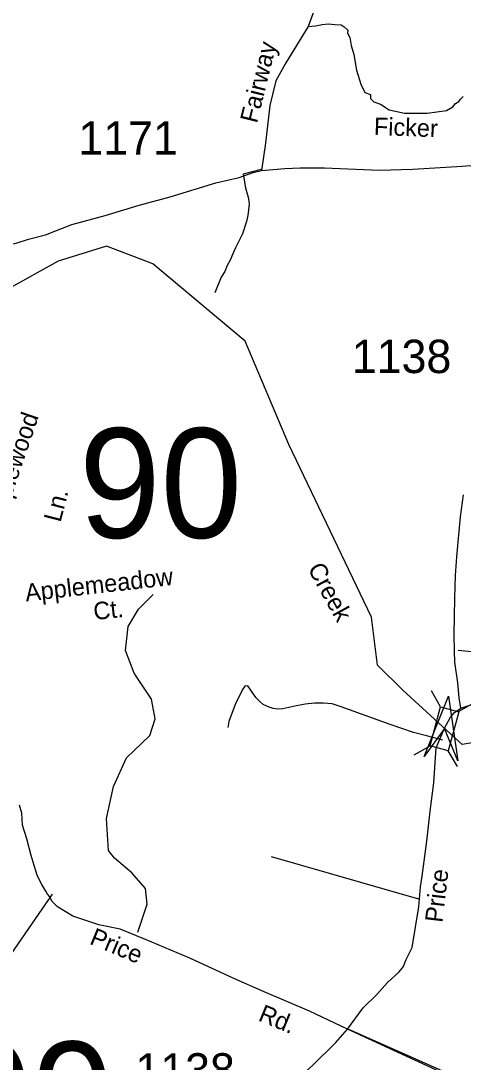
# Model space of a CAD drawing. Extents: x 884530 to 1028605, y 526725 to 653634.
# Drawn here: x 959170 to 960824, y 578430 to 582326 of the extents above; entities that cross this region are included whole.
import ezdxf

# ---------------------------------------------------------------- set-up
doc = ezdxf.new("R2010")
doc.units = 0
for name, color, linetype in [('Exist Hydrographic Creek Single Shore', 7, 'Continuous'), ('Exist Hydrographic Creek Single Shore Label', 7, 'Continuous'), ('Exist Road Non-System Type 51', 7, 'Continuous'), ('Exist Road Non-System Type 51 Label', 7, 'Continuous'), ('Exist Road Secondary Structure Standard Bridge Attributed CELL', 7, 'Continuous'), ('Exist Road Secondary Structure Standard Bridge CELL', 7, 'Continuous'), ('Exist Road Secondary Structure Standard Bridge Number Label', 7, 'Continuous'), ('Exist Road Secondary Type 41 Attributed', 7, 'Continuous'), ('Exist Road Secondary Type 51 Attributed', 7, 'Continuous'), ('Exist Road Secondary Type 51 Label', 7, 'Continuous'), ('Exist Road Secondary Type 51 Number Label', 7, 'Continuous')]:
    doc.layers.add(name, color=color, linetype=linetype)

msp = doc.modelspace()

# ---------------------------------------------------------------- linework, layer by layer
at = {"layer": 'Exist Hydrographic Creek Single Shore'}
msp.add_lwpolyline([(961320.5, 579627.6), (961311.7, 579618.6), (961235.3, 579586.3), (961201.6, 579581.8), (961157.8, 579589.6), (961042.1, 579604.3), (960967.9, 579615.5), (960925.2, 579632.4), (960888.2, 579629), (960821.3, 579618.6), (960598.8, 579821), (960504.4, 579915.4), (960482.1, 580094.7), (960172.1, 580740.4), (960009.5, 581126.8), (959664, 581416.7), (959491.2, 581482.7), (959310.4, 581426), (958932.1, 581217.6)], dxfattribs=at)
at = {"layer": 'Exist Road Non-System Type 51'}
for p, q in [((960069.3, 581769.7), (960001.9, 581752.5)), ((960658.8, 579039.8), (960107.6, 579197.8)), ((960395.8, 578553.7), (960822.7, 578364.1))]:
    msp.add_line(p, q, dxfattribs=at)
for points in [[(960001.9, 581752.5), (960010.2, 581701.1), (960020.7, 581666.4), (960024.7, 581640.6), (960022.3, 581618.9), (960019.9, 581597.1), (960014.3, 581574.5), (959999.9, 581529), (959985.2, 581500.9), (959973.2, 581477), (959962.9, 581454.3), (959953, 581430.3), (959942.5, 581410.9), (959932.8, 581388.3), (959920, 581366.5), (959895.6, 581307.9)], [(959608.4, 578915.5), (959643.3, 579021.1), (959636.8, 579079.4), (959585, 579137.7), (959520.3, 579192.7), (959497.7, 579221.8), (959491.2, 579341.5), (959517, 579461.3), (959565.6, 579568.1), (959653, 579652.3), (959672.5, 579713.8), (959659.5, 579788.3), (959594.7, 579885.4), (959562.3, 579969.5), (959572.1, 580060.2), (959610.9, 580124.9), (959665.9, 580180)], [(960805.6, 579970.5), (961100.7, 579940.7), (961165, 579984.5)], [(960748.6, 579634.1), (960692.8, 579649.9), (960638.4, 579663.3), (960551.7, 579693.3), (960368.3, 579758.9), (960335, 579770), (960302.5, 579773.3), (960268.6, 579773.3), (960233.7, 579768.6), (960195, 579761.6), (960149.7, 579751.8), (960129.8, 579750.1), (960113.4, 579752.6), (960098.6, 579757.5), (960077.1, 579767.4), (960064.8, 579778.1), (960049.7, 579793.8), (960044.3, 579801.5), (960019.5, 579837.6), (960008.6, 579836.4), (959999.9, 579824.5), (959972.1, 579768.4), (959947.7, 579704.8), (959944.9, 579682.2)], [(959288, 579058.1), (959015.3, 578664.8), (958396.6, 579235.8)]]:
    msp.add_lwpolyline(points, dxfattribs=at)
at = {"layer": 'Exist Road Secondary Structure Standard Bridge Attributed CELL'}
msp.add_lwpolyline([(960678.7, 579572.7), (960770.1, 579798.8), (960804, 579557.4), (960755.2, 579677.8)], close=True, dxfattribs=at)
at = {"layer": 'Exist Road Secondary Structure Standard Bridge CELL'}
for p, q in [((960740, 579759.2), (960705.5, 579819)), ((960806.7, 579741.4), (960866.4, 579775.9)), ((960640.8, 579578.9), (960700.6, 579613.4)), ((960803.3, 579535.3), (960768.8, 579595.1))]:
    msp.add_line(p, q, dxfattribs=at)
msp.add_lwpolyline([(960700.6, 579613.4), (960739.7, 579759.3), (960807.9, 579741), (960768.8, 579595.1)], close=True, dxfattribs=at)
at = {"layer": 'Exist Road Secondary Type 41 Attributed'}
msp.add_lwpolyline([(960244.6, 582304.3), (960272.6, 582307.3), (960296.8, 582311.5), (960320.1, 582314.1), (960344.9, 582311.9), (960368.9, 582311.2), (960379.2, 582303.6), (960392.7, 582291.2), (960392, 582280.1), (960401.3, 582263.7), (960405.4, 582233.8), (960415.8, 582200.1), (960426.1, 582140.6), (960441.7, 582088.8), (960457.2, 582057.8), (960478.4, 582050), (960477.9, 582034.5), (960490.1, 582022.9), (960515.7, 582014), (960547.7, 581993), (960604.6, 581980.1), (960690, 581980.1), (960762.5, 581990.4), (960785.7, 582003.4), (960795.6, 582017), (960807.8, 582024.5), (960814.2, 582032.2), (960824.6, 582042)], dxfattribs=at)
at = {"layer": 'Exist Road Secondary Type 51 Attributed'}
for points in [[(960315.1, 582621.7), (960310.9, 582515.8), (960285, 582414.8), (960244.6, 582304.3)], [(960244.6, 582304.3), (960160.8, 582168.9), (960124.6, 582101.6), (960101.3, 582008.4), (960085.8, 581868.6), (960070.3, 581765.7)], [(958796, 581318.2), (958919.8, 581421.4), (958962.8, 581449.9), (959005.6, 581470.4), (959058.8, 581473.1), (959105.3, 581483.5), (959152.4, 581494.3), (959198.9, 581508.8), (959263.1, 581524.9), (959361.5, 581563.7), (959486, 581597.9), (959613.4, 581635.6), (959728.8, 581667.3), (959899.6, 581719.1), (959986.9, 581739.1), (960039.3, 581757.9), (960070.3, 581765.7)], [(960070.3, 581765.7), (960158.2, 581772.8), (960215.1, 581775.4), (960305.6, 581775.4), (960509.8, 581766.4), (960636, 581770.5), (960821.3, 581781.9), (960933.8, 581790.3)], [(960816.3, 579754.4), (960809.1, 579793.2), (960805, 579849.3), (960793.2, 579925.6), (960792.6, 579967.6), (960790.9, 580029.7), (960793.6, 580165.7), (960795.9, 580250.9), (960800.3, 580320.8), (960814.9, 580470.4), (960826.2, 580552.9)], [(960816.3, 579754.4), (960853.4, 579766.5), (960868.6, 579768.5), (960893, 579775.8), (960912.2, 579775), (960948.3, 579777.7), (960991.2, 579773.6), (961038.8, 579767.8), (961090.3, 579763.7), (961168.3, 579761), (961201.4, 579768.7), (961254.3, 579787.2)], [(960754.9, 579679), (960777.6, 579720), (960792.2, 579737.5), (960816.3, 579754.4)], [(960391.7, 578552.9), (960450.3, 578632.5), (960502.1, 578682.7), (960541.6, 578727.5), (960585, 578767.9), (960601.8, 578787.3), (960606.3, 578801.2), (960611.4, 578814), (960633.8, 578858.6), (960658.5, 579010.9), (960665.5, 579085.7), (960670.9, 579125.4), (960689.1, 579257), (960701.1, 579368.3), (960714.8, 579474.4), (960724.1, 579605.7), (960754.9, 579679)], [(960391.7, 578552.9), (960250.2, 578620.9), (960080.8, 578692.6), (959967.4, 578743.1), (959802, 578818.2), (959636.6, 578888.7), (959541.6, 578927.1), (959462, 578943.9), (959365.5, 578976.1), (959307.3, 579011.4), (959286, 579032.4), (959278.3, 579047.8), (959270.6, 579058.5), (959264.5, 579069.2), (959249.5, 579094.4), (959232.5, 579125), (959220.3, 579165.1), (959209.4, 579202.6), (959193.2, 579265.3), (959176.8, 579316.1), (959174.4, 579361.3), (959165.5, 579390.6)], [(959898.1, 578032.9), (959962.8, 578099.8), (960053.8, 578198.5), (960190.4, 578353.3), (960260.9, 578417), (960348.2, 578502.9), (960391.7, 578552.9)], [(961150.1, 578206.1), (960891.3, 578328), (960816.4, 578357.9), (960391.7, 578552.9)]]:
    msp.add_lwpolyline(points, dxfattribs=at)

# ---------------------------------------------------------------- texts
at = {"layer": 'Exist Hydrographic Creek Single Shore Label'}
msp.add_text('Creek', height=65.62, rotation=298.7862, dxfattribs=at).set_placement((960241.5, 580276.4))
msp.add_text('Creek', height=65.62, rotation=298.7862, dxfattribs=at).set_placement((960241.5, 580276.4))
at = {"layer": 'Exist Road Non-System Type 51 Label'}
for s, height, rotation, p in [('Applewood', 65.62, 71.1087, (959098, 580435.9)), ('Ln.', 65.62, 75.5699, (959318.7, 580446.9)), ('Applemeadow', 65.617, 6.426, (959189.9, 580153.2)), ('Ct.', 65.62, 6.426, (959445.5, 580083.3))]:
    msp.add_text(s, height=height, rotation=rotation, dxfattribs=at).set_placement(p)
at = {"layer": 'Exist Road Secondary Structure Standard Bridge Number Label'}
for s, p in [('90', (959388, 580391.3)), ('99', (958908.7, 578096.1))]:
    msp.add_text(s, height=410.1, dxfattribs=at).set_placement(p)
at = {"layer": 'Exist Road Secondary Type 51 Label'}
for s, rotation, p in [('Fairway', 76.1159, (960053.2, 581940)), ('Ficker', 357.9478, (960489.8, 581898.8)), ('Price', 83.294, (960746.7, 578949.8)), ('Price', 337.4714, (959423.9, 578873.3)), ('Rd.', 337.5483, (960054.7, 578586.7))]:
    msp.add_text(s, height=65.62, rotation=rotation, dxfattribs=at).set_placement(p)
at = {"layer": 'Exist Road Secondary Type 51 Number Label'}
for s, p in [('1171', (959385.8, 581825.1)), ('1138', (960408.2, 581007.8)), ('1138', (959599, 578338.2))]:
    msp.add_text(s, height=125, dxfattribs=at).set_placement(p)

doc.saveas('drawing.dxf')
